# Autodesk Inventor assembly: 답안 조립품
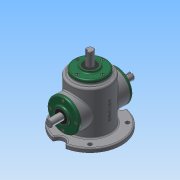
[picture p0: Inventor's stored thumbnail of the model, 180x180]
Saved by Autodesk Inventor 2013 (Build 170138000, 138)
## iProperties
Created: 2018-04
Part Number: 답안 조립품
Document SubType Name: Assembly
Designer: Administrator
Author: Administrator
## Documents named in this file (16)
- C:\Users\Administrator\Desktop\480408V1007\답안 조립품.iam
- C:\Users\Administrator\Desktop\480408V1007\본체.ipt
- C:\Users\Administrator\Desktop\480408V1007\메인 축.ipt
- 메인 축.ipt
- C:\Users\Administrator\Desktop\480408V1007\서브 축.ipt
- 서브 축.ipt
- C:\Users\Administrator\Desktop\480408V1007\키 5x5.ipt
- C:\Users\Administrator\Desktop\480408V1007\키 4x4.ipt
- C:\Users\Administrator\Desktop\480408V1007\베어링 6203.ipt
- C:\Users\Administrator\Desktop\480408V1007\메인 베벨기어.ipt
- C:\Users\Administrator\Desktop\480408V1007\서브 베벨기어.ipt
- C:\Users\Administrator\Desktop\480408V1007\커버.ipt
- C:\Users\Administrator\Desktop\480408V1007\오일 실.ipt
- 오일 실.ipt
- C:\Users\Administrator\Desktop\480408V1007\볼트 M4.ipt
- 볼트 M4.ipt
